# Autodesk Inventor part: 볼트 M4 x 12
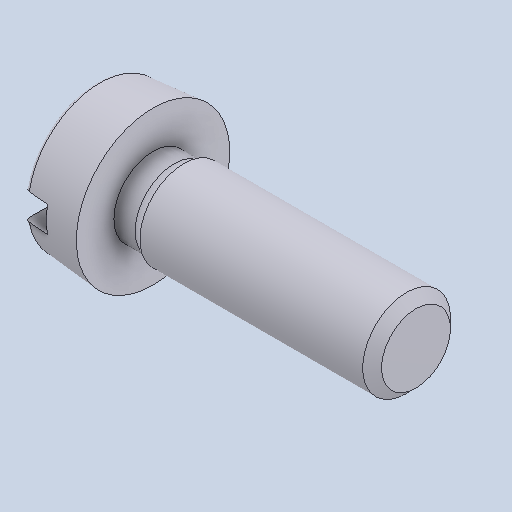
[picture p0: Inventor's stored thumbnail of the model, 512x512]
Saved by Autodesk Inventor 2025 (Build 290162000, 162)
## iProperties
Created: 2025-08
Part Number: 볼트 M4 x 12
Material: 강철, 연강
Description: 6각머리 태핑 나사
Document SubType Name: Modeling
Designer: infra028
Density: 7.85 g/cm^3
Appearance: 기본값
Author: jhkim
Sending System: Autodesk Inventor 2026
Preprocessor: ST-DEVELOPER v20.1
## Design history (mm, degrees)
feature "Solid1"
node "솔리드1"
